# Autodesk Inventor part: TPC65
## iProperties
Shininess: 64.0
Length Units: 11272
Angle Units: 11279
Time Units: 11290
Mass Units: 11286
Length Display Precision: 3
Angle Display Precision: 2
Compacted: True
Part Number: TPC65
Document SubType Name: Modeling
Created: 2004-08
Designer: Lori
Manufacturer: Standard
Standards Organization: Custom
Density: 0.0
Volumn: 0.0
Area: 0.0
PropertySet Name: Model Information
Control State: 0
Master: False
Checked Out: False
Author: Lori
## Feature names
1. Base1
